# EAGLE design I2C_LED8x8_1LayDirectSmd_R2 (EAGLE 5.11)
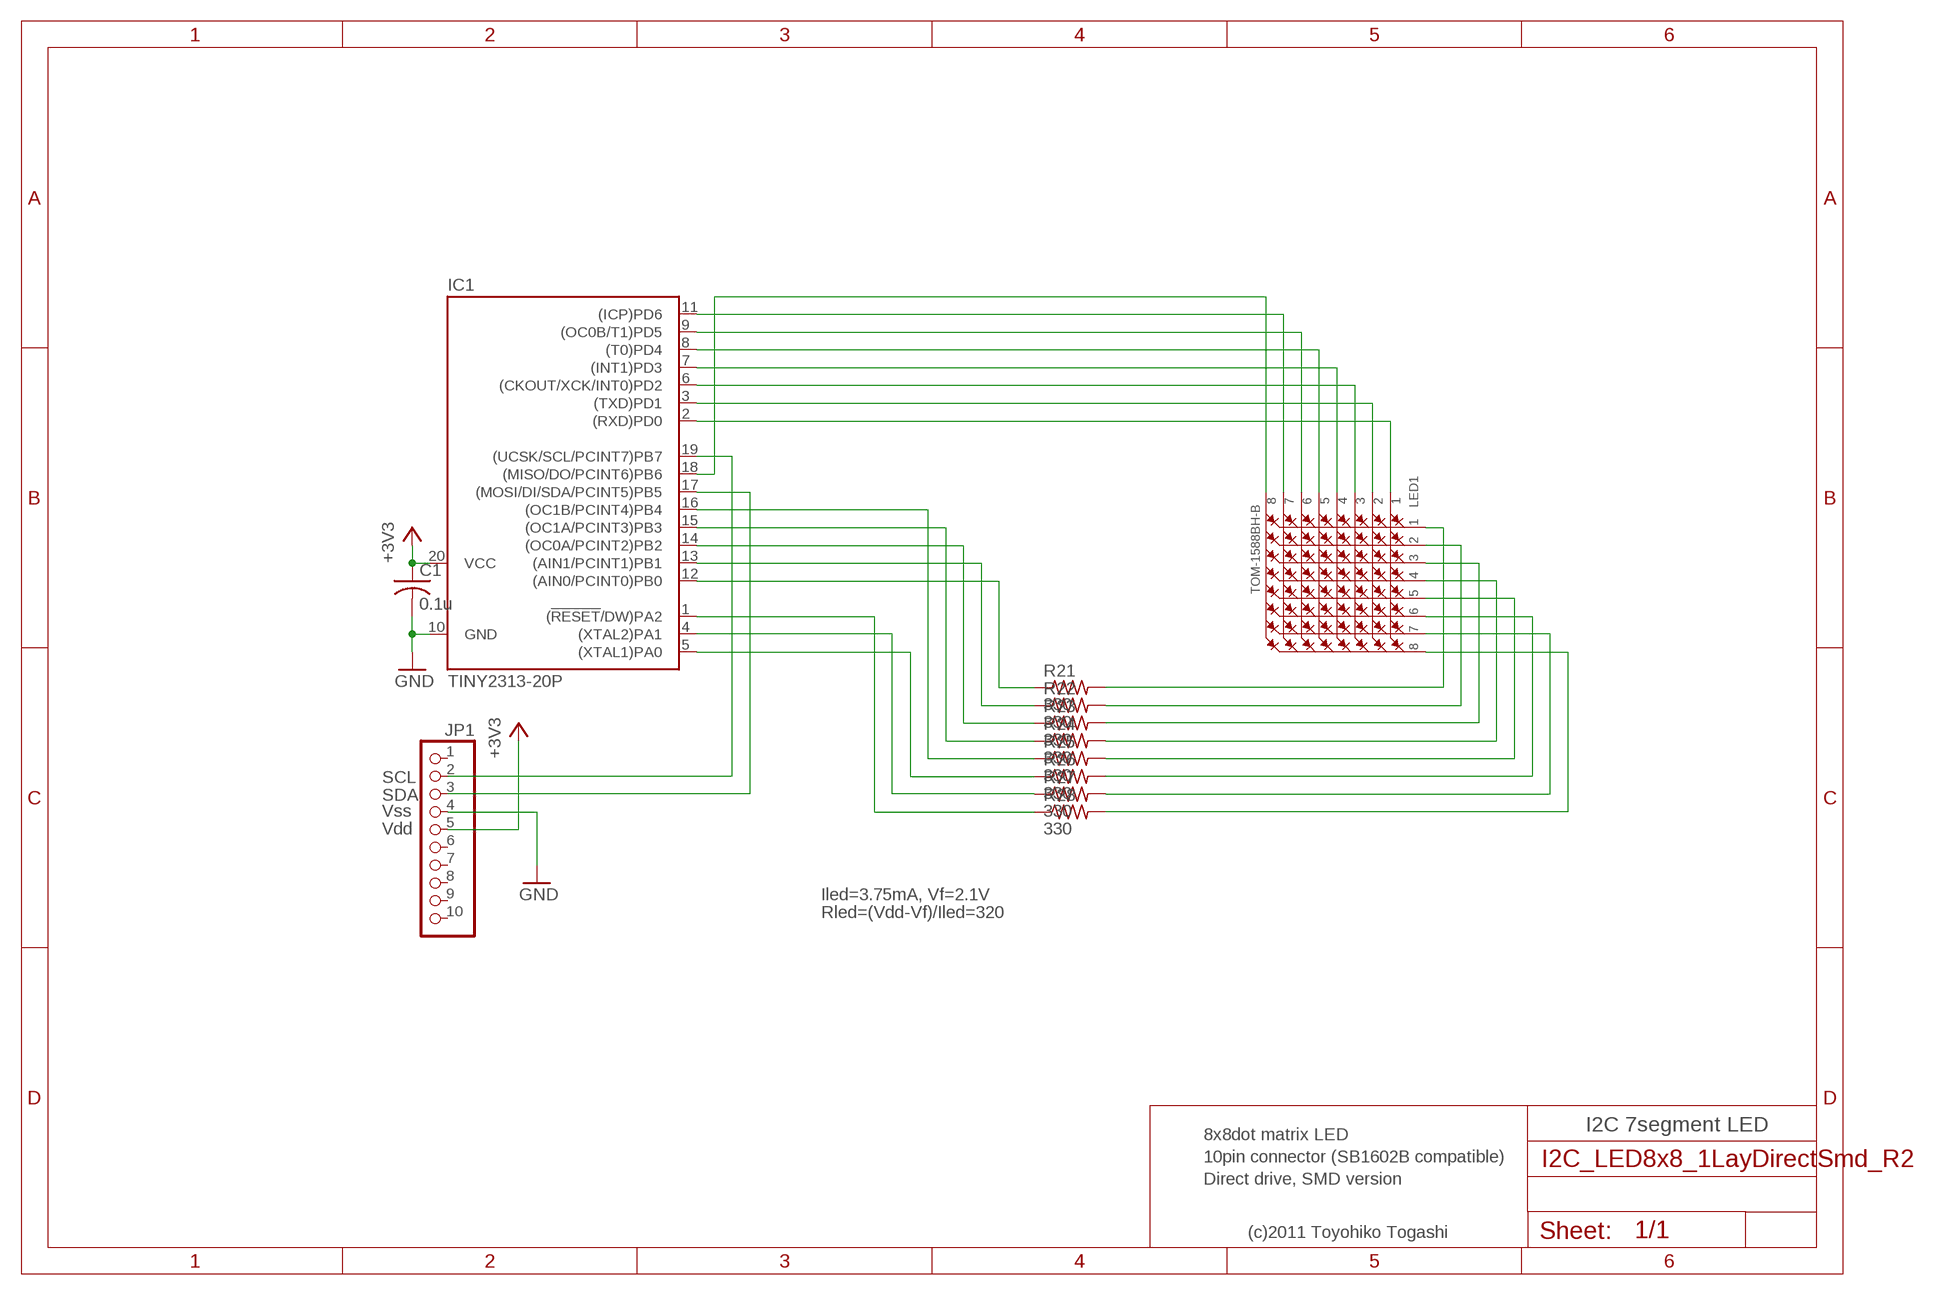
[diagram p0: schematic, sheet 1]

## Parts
C1  0.1u  C-USC0805  [C0805]
IC1  TINY2313-20P  [DIL20]
JP1  PINHD-1X10  [1X10]
LED1  TOM-1588BH-B  [C-4880X]
R21  330  R-US_R0805  [R0805]
R22  330  R-US_R0805  [R0805]
R23  330  R-US_R0805  [R0805]
R24  330  R-US_R0805  [R0805]
R25  330  R-US_R0805  [R0805]
R26  330  R-US_R0805  [R0805]
R27  330  R-US_R0805  [R0805]
R28  330  R-US_R0805  [R0805]

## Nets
+3V3: C1.1 IC1.20(VCC) JP1.5
GND: C1.2 IC1.10(GND) JP1.4
N$1: LED1.P$13(COL1) R21.2
N$2: LED1.P$3(COL2) R22.2
N$3: IC1.19((UCSK/SCL/PCINT7)PB7) JP1.2
N$4: IC1.17((MOSI/DI/SDA/PCINT5)PB5) JP1.3
N$5: LED1.P$4(COL3) R23.2
N$6: LED1.P$10(COL4) R24.2
N$7: LED1.P$6(COL5) R25.2
N$8: LED1.P$11(COL6) R26.2
N$9: LED1.P$15(COL7) R27.2
N$10: LED1.P$16(COL8) R28.2
N$14: IC1.5((XTAL1)PA0) R26.1
N$15: IC1.4((XTAL2)PA1) R27.1
N$16: IC1.1((!RESET!/DW)PA2) R28.1
N$17: IC1.12((AIN0/PCINT0)PB0) R21.1
N$19: IC1.13((AIN1/PCINT1)PB1) R22.1
N$20: IC1.14((OC0A/PCINT2)PB2) R23.1
N$21: IC1.15((OC1A/PCINT3)PB3) R24.1
N$22: IC1.16((OC1B/PCINT4)PB4) R25.1
N$25: IC1.18((MISO/DO/PCINT6)PB6) LED1.P$5(ROW8)
N$28: IC1.2((RXD)PD0) LED1.P$9(ROW1)
N$50: IC1.3((TXD)PD1) LED1.P$14(ROW2)
N$53: IC1.7((INT1)PD3) LED1.P$12(ROW4)
N$54: IC1.9((OC0B/T1)PD5) LED1.P$7(ROW6)
N$98: IC1.11((ICP)PD6) LED1.P$2(ROW7)
N$100: IC1.8((T0)PD4) LED1.P$1(ROW5)
N$102: IC1.6((CKOUT/XCK/INT0)PD2) LED1.P$8(ROW3)
Unconnected: JP1.1 JP1.6 JP1.7 JP1.8 JP1.9 JP1.10

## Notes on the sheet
- SCL
- SDA
- Vss
- Vdd
- Iled=3.75mA, Vf=2.1V
- Rled=(Vdd-Vf)/Iled=320
- I2C 7segment LED
- 8x8dot matrix LED
- 10pin connector (SB1602B compatible)
- Direct drive, SMD version
- (c)2011 Toyohiko Togashi

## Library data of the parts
C1 = rcl:C-US: CAPACITOR, American symbol
IC1 = TOG:TINY2313: 8-bit AVR Microcontroller with 2K Bytes Flash Source: http://www.atmel.com .. doc2543.pdf
JP1 = pinhead:PINHD-1X10: PIN HEADER
LED1 = TOG:TOM-1588BH-B: PARALIGHT C-4880X 1.5x1.5inch 8x8dot matrix
R21-R28 = rcl:R-US_: RESISTOR, American symbol

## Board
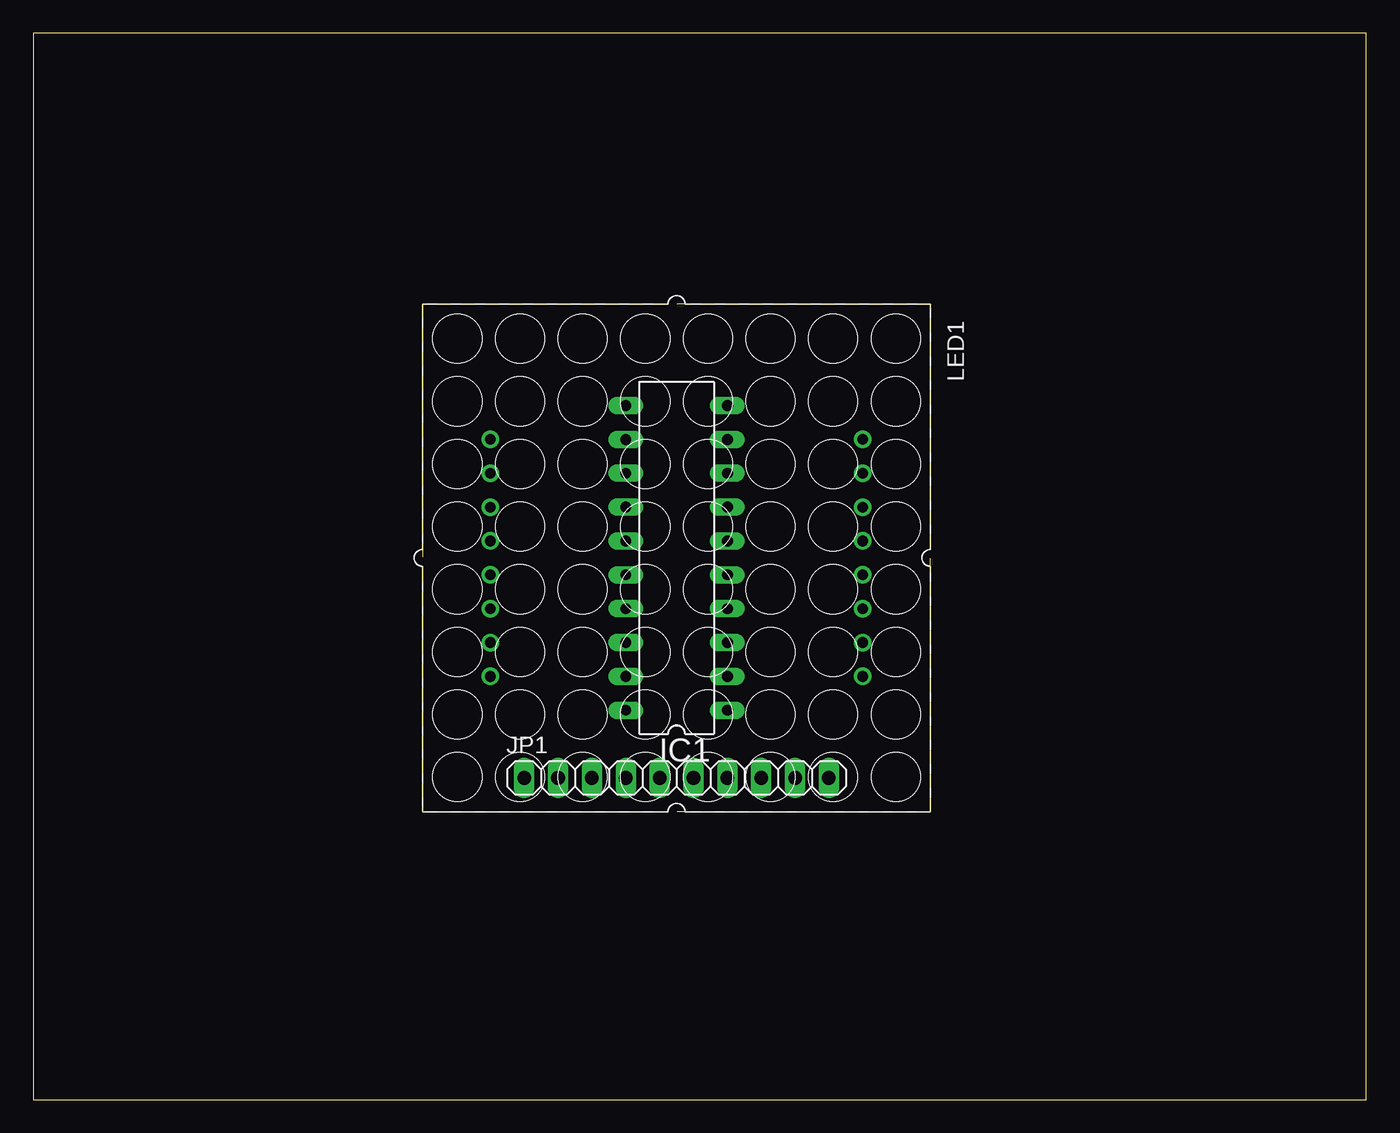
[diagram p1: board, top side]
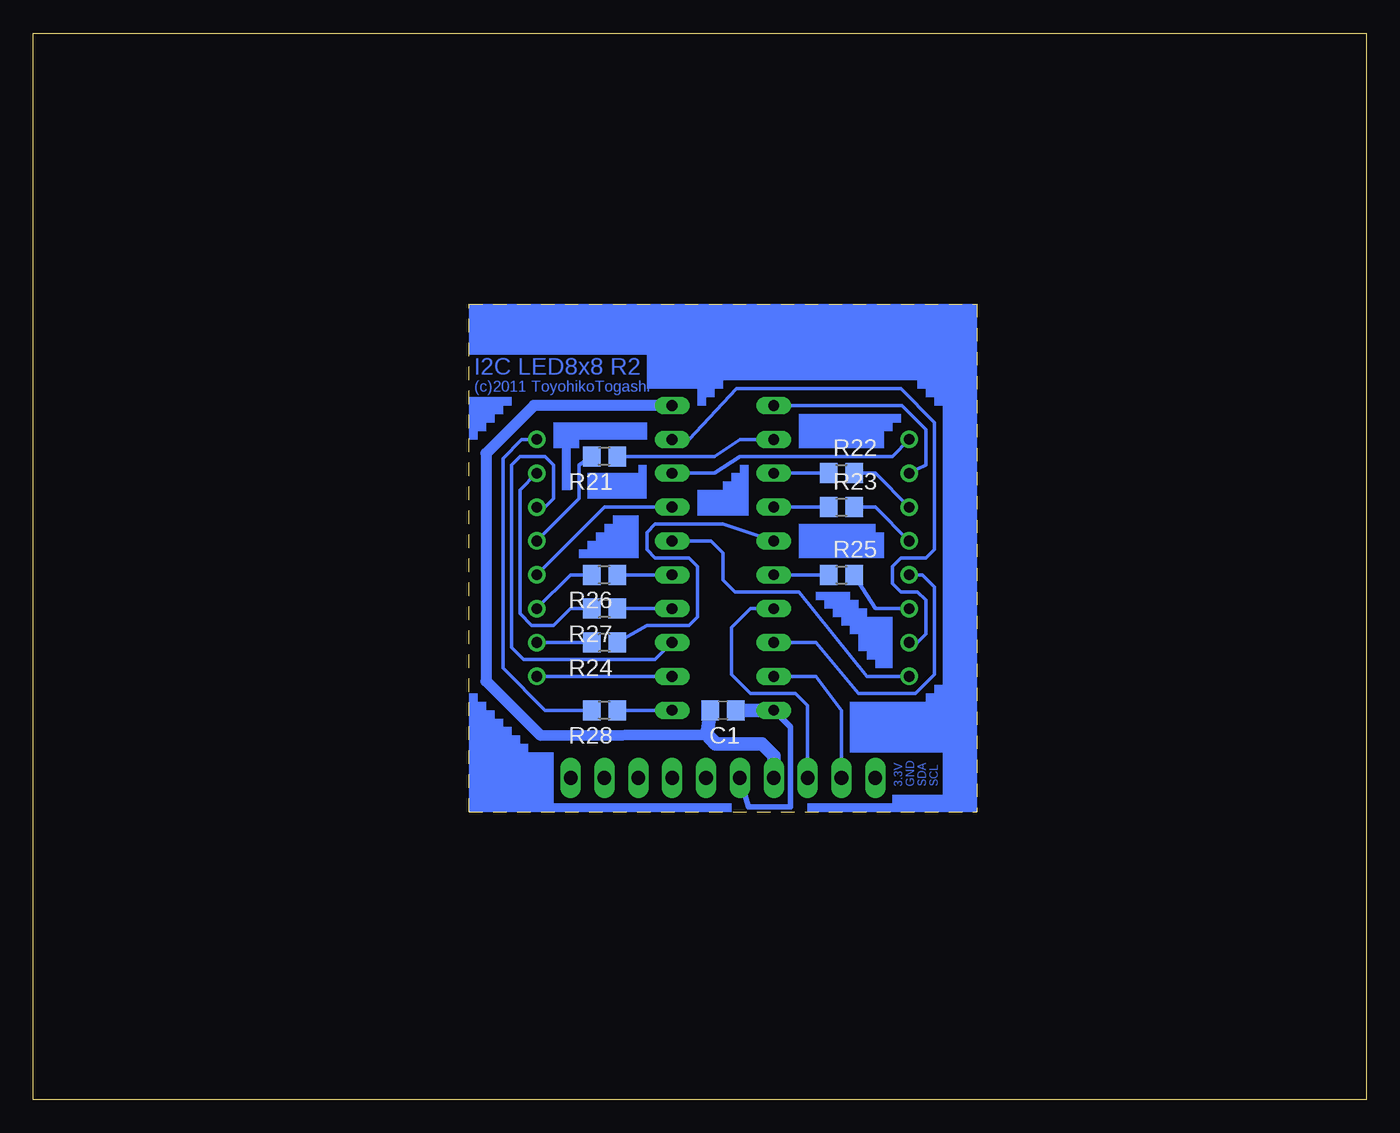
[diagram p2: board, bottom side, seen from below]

Size 100 x 80 mm. Coordinates in mm from the lower left corner, seen from the top.
Outline: 0,0 100,0 100,80 0,80 0,0
Outline: 29.21,59.69 29.21,21.59 67.31,21.59 67.31,59.69 29.21,59.69
Copper layers (1*16): Top 0.035mm / dielectric 1.5mm / Bottom 0.035mm
Design rules "default": minimum track width 10mil, minimum drill 24mil, track to track 8mil, track to pad 8mil, pad to pad 8mil, via to via 8mil, smd to smd 8mil, copper to edge 40mil, drill to drill 8mil, minimum pad ring 10mil, minimum via ring 8mil, stop-mask expansion 4mil, vias tented up to drill 0mil, thermal gap 10mil

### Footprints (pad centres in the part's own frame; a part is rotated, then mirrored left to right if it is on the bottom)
C0805 = smd 1.3 x 1.5: 1 -0.95,0; 2 0.95,0
DIL20@1 = drill 0.813 long: 1 -11.43,-3.81; 2 -8.89,-3.81; 3 -6.35,-3.81; 4 -3.81,-3.81; 5 -1.27,-3.81; 6 1.27,-3.81; 7 3.81,-3.81; 8 6.35,-3.81; 9 8.89,-3.81; 10 11.43,-3.81; 11 11.43,3.81; 12 8.89,3.81; 13 6.35,3.81; 14 3.81,3.81; 15 1.27,3.81; 16 -1.27,3.81; 17 -3.81,3.81; 18 -6.35,3.81; 19 -8.89,3.81; 20 -11.43,3.81
1X10 = drill 1.016 long: 1 -11.43,0; 2 -8.89,0; 3 -6.35,0; 4 -3.81,0; 5 -1.27,0; 6 1.27,0; 7 3.81,0; 8 6.35,0; 9 8.89,0; 10 11.43,0
C-4880X = drill 0.8 round: P$1 -8.89,-13.97; P$2 -6.35,-13.97; P$3 -3.81,-13.97; P$4 -1.27,-13.97; P$5 1.27,-13.97; P$6 3.81,-13.97; P$7 6.35,-13.97; P$8 8.89,-13.97; P$9 8.89,13.97; P$10 6.35,13.97; P$11 3.81,13.97; P$12 1.27,13.97; P$13 -1.27,13.97; P$14 -3.81,13.97; P$15 -6.35,13.97; P$16 -8.89,13.97
R0805 = smd 1.3 x 1.5: 1 -0.95,0; 2 0.95,0

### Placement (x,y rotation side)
C1  48.26,29.21 180 bottom
IC1  TINY2313-20P  [DIL20@1]  48.26,40.64 90 top
JP1  48.26,24.13 0 top
LED1  48.26,40.64 270 top
R21  57.15,48.26 180 bottom
R22  39.37,46.99 0 bottom
R23  39.37,44.45 0 bottom
R24  57.15,34.29 180 bottom
R25  39.37,39.37 0 bottom
R26  57.15,39.37 180 bottom
R27  57.15,36.83 180 bottom
R28  57.15,29.21 180 bottom

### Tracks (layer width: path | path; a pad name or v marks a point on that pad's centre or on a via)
+3V3
  Bottom 0.406: JP1.5 46.35,21.97 43.18,21.97 43.18,27.94 IC1.20
  Bottom 1.016: IC1.20 C1.1
GND
  Bottom 0.813: IC1.10 62.45,52.07 66.04,48.48 66.04,31.39 61.95,27.32 49.44,27.38
  Bottom 1.016: JP1.4 44.45,25.77 45.35,26.67 48.81,26.67 49.44,27.38 C1.2
N$1
  Bottom 0.254: LED1.P$13 59.05,45.09 59.05,47.62 R21.2
N$2
  Bottom 0.254: R22.2 36.83,46.99 LED1.P$3
N$3
  Bottom 0.254: JP1.2 39.37,29.21 41.27,31.75 IC1.19
N$4
  Bottom 0.254: JP1.3 41.91,29.58 42.81,30.48 46.2,30.48 47.62,31.9 47.62,35.41 46.2,36.83 IC1.17
N$5
  Bottom 0.254: LED1.P$4 36.83,44.45 R23.2
N$6
  Bottom 0.254: LED1.P$10 R24.2
N$7
  Bottom 0.254: LED1.P$6 36.83,36.83 R25.2
N$8
  Bottom 0.254: LED1.P$11 59.69,39.37 R26.2
N$9
  Bottom 0.254: R27.2 59.69,36.83 60.96,35.56 62.6,35.56 63.5,36.46 63.5,45.72 LED1.P$15
N$10
  Bottom 0.254: R28.2 61.59,29.21 64.77,32.38 64.77,48.11 63.35,49.53 LED1.P$16
N$14
  Bottom 0.254: R26.1 IC1.5
N$15
  Bottom 0.254: R27.1 IC1.4
N$16
  Bottom 0.254: IC1.1 R28.1
N$17
  Bottom 0.254: R21.1 48.9,48.26 46.99,49.53 IC1.12
N$19
  Bottom 0.254: R22.1 IC1.13
N$20
  Bottom 0.254: R23.1 IC1.14
N$21
  Bottom 0.254: R24.1 53.98,35.56 50.8,35.56 50.16,36.2 50.16,40.01 50.8,40.64 53.34,40.64 53.98,41.27 53.98,42.55 53.34,43.18 48.26,43.18 IC1.15
N$22
  Bottom 0.254: IC1.16 R25.1
N$25
  Bottom 0.254: LED1.P$5 33.28,39.37 32.38,38.47 32.38,31.9 33.8,30.48 38.1,30.48 41.27,34.29 IC1.18
N$28
  Bottom 0.254: IC1.2 LED1.P$9
N$50
  Bottom 0.254: IC1.3 53.34,33.02 63.24,33.02 64.14,33.92 64.14,47.62 63.5,48.26 61.59,48.26 60.96,47.62 60.96,45.09 61.59,44.45 LED1.P$14
N$53
  Bottom 0.254: LED1.P$12 57.15,44.45 IC1.7
N$54
  Bottom 0.254: LED1.P$7 33.66,34.29 33.02,34.92 33.02,37.47 33.66,38.1 34.92,38.1 35.56,38.73 35.56,40.01 34.92,40.64 33.02,40.64 32.38,41.27 32.38,50.8 34.92,53.34 47.24,53.34 50.8,49.53 IC1.9
N$98
  Bottom 0.254: LED1.P$2 33.02,47.62 33.02,50.27 34.82,52.07 IC1.11
N$100
  Bottom 0.254: LED1.P$1 35.56,48.26 46.99,48.26 48.9,46.99 IC1.8
N$102
  Bottom 0.254: LED1.P$8 37.47,31.75 42.55,38.1 47.36,38.1 48.26,39 48.26,41.01 49.16,41.91 IC1.6
(copper drawn outside any net)
  shapes: Bottom area x57

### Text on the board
Bottom: I2C LED8x8 R2 | (c)2011 ToyohikoTogashi | SCL | SDA | GND | 3.3V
